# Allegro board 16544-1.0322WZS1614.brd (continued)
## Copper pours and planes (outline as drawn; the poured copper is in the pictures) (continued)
AMP_SPKR_L-_C on TOP: 216.41,5.26 216.41,8.99 216.13,9.27 216.13,11.07 216.2,11.15 218.31,11.15 218.59,10.87 218.59,10.34 218.39,10.14 217.86,10.14 217.84,10.12 217.69,10.12 217.09,9.53 217.09,5.28 217.07,5.26
AMP_SPKR_R+_C on TOP: 213.39,5.23 213.23,5.38 213.23,8.76 212.88,9.12 210.26,9.12 210.25,9.11 208.39,9.11 207.47,10.03 205.87,10.03 205.49,10.41 205.49,12.6 205.64,12.75 206.76,12.75 206.88,12.88 208.64,12.88 208.66,12.85 208.66,10.46 208.97,10.16 213.23,10.16 214.25,9.14 214.25,5.38 214.1,5.23 ; 1 cut-out
AMP_SPKR_R-_C on TOP: 214.91,5.26 214.91,8.74 214.9,8.75 214.9,9 214.88,9.02 214.88,9.19 213.61,10.46 213.18,10.46 213.06,10.59 213.06,11.2 213.27,11.42 215.56,11.42 215.77,11.2 215.77,8.94 215.6,8.76 215.6,5.26
AUO_PVDD1 on BOTTOM: 194.36,41.1 194.06,41.4 193.29,41.4 193.22,41.48 193.22,43.03 193.68,43.48 197.97,43.48 198.12,43.33 198.12,41.53 197.99,41.4 195.33,41.4 195.02,41.1 ; 4 cut-outs
DC_19V on TOP: 29.49,110.24 29.34,110.39 29.34,112.01 27.81,113.54 27.81,123.44 27.94,123.57 33.02,123.57 33.71,122.89 33.71,110.69 33.25,110.24 ; 2 cut-outs
DC_19V on BOTTOM: 29.03,112.45 27.81,113.67 27.81,123.06 28.07,123.32 32.64,123.32 33.53,122.43 33.53,112.65 33.32,112.45 ; 1 cut-out
EC_3D3V_AUX_S5 on TOP: 101.85,74.93 101.6,75.18 100.97,75.18 100.84,75.31 100.84,75.69 101.09,75.95 102.36,75.95 103.12,76.71 103.12,77.98 102.87,78.23 100.58,78.23 100.2,78.61 100.2,79.5 100.33,79.63 100.33,81.03 100.46,81.15 102.87,81.15 104.01,80.01 104.01,75.95 103,74.93 ; 3 cut-outs
IPCC_AGND on BOTTOM: 17.6,132.08 16.66,133.02 16.66,135.87 16.26,136.27 15.88,136.27 15.75,136.4 15.75,136.78 15.88,136.91 16.28,136.91 16.66,137.29 16.66,139.01 16.92,139.27 21.06,139.27 21.44,138.89 21.44,137.21 21.67,136.98 21.67,134.84 21.51,134.68 18.61,134.68 18.24,134.32 18.24,133.71 18.8,133.15 18.8,133.1 19.05,132.84 19.05,132.33 18.8,132.08 ; 6 cut-outs
Net_67 on BOTTOM: 119,84.45 119,83.31 123.44,83.31 123.44,84.45
Net_68 on BOTTOM: 125.04,56.39 129.62,56.39 129.62,58.39 125.04,58.39
PWR_0D8V on TOP: 115.04,192.56 114.68,192.91 114.68,193.22 113.46,194.44 113.46,197.89 113.67,198.09 119.28,198.09 119.58,197.79 119.58,192.91 119.23,192.56
PWR_0D8V on BOTTOM: 113.64,192.02 113.46,192.2 113.46,197.89 113.67,198.09 119.28,198.09 119.58,197.79 119.58,193.55 119.41,193.37 119.41,192.48 119.1,192.18 117.32,192.18 117.2,192.3 115.14,192.3 114.86,192.02
PWR_0D8V_FB_A on BOTTOM: 119.76,205.87 119.38,206.25 119.38,207.14 119.63,207.39 121.41,207.39 121.54,207.26 121.54,206.88 120.52,205.87 ; 1 cut-out
PWR_0D8V_PH on TOP: 114.76,199.31 113.84,200.23 113.84,203.07 114.22,203.45 118.82,203.45 119.1,203.17 119.1,200 118.41,199.31
PWR_0D8V_PH on BOTTOM: 114.54,199.63 113.69,200.48 113.69,202.37 113.35,202.72 112.62,202.72 112.52,202.82 112.52,203.38 113.82,204.67 113.92,204.67 114.07,204.83 114.12,204.83 114.55,205.26 114.71,205.26 114.81,205.16 114.81,203.66 115.42,203.05 118.08,203.05 118.41,202.72 118.41,200 118.05,199.63 ; 1 cut-out
PWR_0D8V_PH on L6: 114.58,208.23 114.58,203.63 115.23,202.98 116.17,202.98 118.75,200.41 118.75,199.64 118.36,199.26 114.68,199.26 113.51,200.43 113.51,208.79 113.56,208.84 113.97,208.84
PWR_0D8V_VCC on BOTTOM: 116.08,203.71 115.54,204.24 115.54,205.33 115.57,205.36 115.7,205.36 115.95,205.1 116.15,205.1 116.23,205.03 116.23,204.83 116.33,204.72 119.13,204.72 119.25,204.6 119.25,203.84 119.13,203.71
PWR_0D9V_VIN on TOP: 138.68,204.98 138.3,205.36 138.3,207.77 137.92,208.15 136.65,208.15 136.4,208.41 136.4,209.68 135.76,210.31 135.76,212.09 136.27,212.6 137.67,212.6 137.79,212.47 137.79,211.33 138.18,210.95 138.18,209.55 138.43,209.3 141.22,209.3 141.35,209.17 141.35,205.23 141.1,204.98 ; 2 cut-outs
PWR_0D775V on TOP: 123.01,207.65 122.86,207.8 122.86,209.91 122.71,210.06 122.71,211.02 122.43,211.3 122.43,213.23 122.68,213.49 123.57,213.49 124.08,212.98 124.08,212.34 123.83,212.09 123.83,209.73 123.52,209.42 123.52,207.87 123.29,207.65 ; 4 cut-outs
PWR_1D2V on TOP: 223.39,97.54 222.94,97.99 222.94,108.76 224.46,110.29 230.33,110.29 231.27,109.35 231.27,107.92 228.6,105.26 228.6,97.92 228.22,97.54
PWR_1D2V on TOP: 229.18,132.03 228.12,133.1 226.31,133.1 226.06,133.35 226.06,134.37 226.19,134.49 227.71,134.49 227.9,134.31 227.9,134.32 230.45,134.32 230.78,133.99 230.78,132.31 230.5,132.03
PWR_1D2V on BOTTOM: 223.39,97.54 222.76,98.17 222.76,108.58 224.49,110.31 230.35,110.31 231.29,109.37 231.29,108.23 230.76,107.7 228.85,107.7 228.6,107.44 228.6,97.92 228.22,97.54
PWR_1D2V on L3: 228.85,133.86 228.85,132.33 229.11,132.08 231.14,132.08 231.78,131.44 232.94,131.44 233.3,131.8 233.3,132.46 231.52,134.24 229.24,134.24
PWR_1D5V on TOP: 140.34,127.38 140.21,127.51 137.85,127.51 137.68,127.67 137.68,129.4 137.79,129.51 137.79,132.44 137.87,132.51 138.79,132.51 139.17,132.13 141.05,132.13 141.1,132.08 141.1,129.41 140.97,129.29 140.97,129.26 140.89,129.18 140.89,127.43 140.84,127.38 ; 6 cut-outs
PWR_1D05V on TOP: 143.61,26.34 143.51,26.44 143.51,33.02 143.13,33.4 143.13,33.78 143.26,33.91 147.12,33.91 147.24,33.78 147.24,32.33 147.7,31.88 147.7,26.67 147.37,26.34
PWR_1D05V on BOTTOM: 143.64,30.35 143.51,30.48 143.51,32.26 144.4,33.15 146.69,33.15 147.7,32.13 147.7,30.61 147.45,30.35
PWR_1D5V_PH on TOP: 146.18,18.29 145.16,19.3 143.76,19.3 143.51,19.56 143.51,22.53 143.87,22.89 147.12,22.89 147.24,22.76 147.24,20.47 147.12,20.35 146.94,20.35 146.48,19.89 146.48,19.51 146.69,19.3 146.69,18.39 146.58,18.29 ; 1 cut-out
PWR_1D5V_PH on BOTTOM: 145.11,14.76 145.03,14.83 145.03,16.38 145.02,16.4 145.02,17.84 144.4,18.47 144.4,19.94 144.58,20.12 146.05,20.12 146.28,19.89 146.28,15.06 145.97,14.76
PWR_1D5V_VIN on TOP: 134.67,125.4 134.49,125.58 134.49,128.47 134.19,128.78 132.59,128.78 132.08,129.29 132.08,131.57 132.49,131.98 134.24,131.98 134.32,131.9 134.32,130.18 134.49,130 136.83,130 137.31,129.51 137.31,125.45 137.26,125.4 ; 2 cut-outs
PWR_1D8V on TOP: 132.74,117.07 131.7,118.11 131.7,122.17 132.21,122.68 137.54,122.68 137.67,122.56 137.67,117.68 137.06,117.07
PWR_1D8V on BOTTOM: 131.95,119.41 131.72,119.63 131.72,122.05 132.23,122.56 136.78,122.56 137.34,122 137.34,119.81 136.93,119.41
PWR_1D8V_PH on TOP: 133.93,109.04 132.87,110.11 132.74,110.11 131.9,110.95 131.9,113.54 132.36,114 136.3,114 136.45,113.84 136.45,111.33 136.32,111.2 135.03,111.2 134.37,110.54 134.37,109.14 134.26,109.04
PWR_1D8V_PH on BOTTOM: 132.84,105.28 132.72,105.41 132.72,109.98 132.33,110.36 132.33,110.87 132.72,111.25 133.35,111.25 133.73,110.87 133.73,105.41 133.6,105.28
PWR_1D8V_VGA on TOP: 95.12,155.32 95.12,156.97 95.38,157.23 95.76,157.23 95.89,157.35 95.89,159.89 95.55,160.22 95.55,160.58 95.61,160.63 97.13,160.63 97.14,160.64 97.57,160.64 98.22,161.29 98.22,162.18 98.3,162.26 99.77,162.26 99.77,162.23 99.85,162.15 99.85,156.36 98.81,155.32 ; 6 cut-outs
PWR_1D8V_VGA_VIN on TOP: 101.47,156.97 100.2,158.24 100.2,162.94 100.46,163.19 102.74,163.19 103,162.94 103,159.89 103.12,159.77 105.03,159.77 106.3,158.5 107.82,158.5 107.95,158.62 108.2,158.62 108.33,158.5 108.33,157.1 108.2,156.97 ; 2 cut-outs
PWR_1D35V on TOP: 34.44,212.7 34.16,212.98 28.83,212.98 28.45,213.36 28.45,219.84 28.96,220.34 36.32,220.34 37.21,219.46 37.21,213.44 36.47,212.7
PWR_1D35V on BOTTOM: 28.7,212.98 28.32,213.36 28.32,220.34 28.96,220.98 36.7,220.98 37.21,220.47 37.21,213.61 36.58,212.98
PWR_1D35V_PH on TOP: 10.67,212.47 10.54,212.6 10.54,213.61 10.29,213.87 10.29,215.39 10.54,215.65 12.19,215.65 12.32,215.52 12.32,214 10.79,212.47 ; 1 cut-out
PWR_1D35V_PH on TOP: 19.38,210.29 19.1,210.57 19.1,215.93 19.28,216.1 22.94,216.1 23.29,216.46 23.29,218.06 22.66,218.69 22.66,222.35 22.81,222.5 26.54,222.5 27.05,222 27.05,210.82 26.52,210.29
PWR_1D35V_PH on BOTTOM: 19.41,210.29 19.18,210.52 19.18,215.65 19.68,216.15 22.48,216.15 22.86,216.53 22.86,222.25 23.11,222.5 26.54,222.5 27.05,222 27.05,210.82 26.52,210.29
PWR_2D5V on TOP: 136.7,71.45 136.55,71.6 136.55,75.97 138.05,77.47 138.81,77.47 138.93,77.36 138.93,75.45 139,75.37 138.99,75.36 138.99,73.71 138.68,73.41 138.68,71.58 138.56,71.45 ; 7 cut-outs
PWR_2D5V_PCH on TOP: 137.34,60.1 137.12,60.31 136.92,60.31 136.91,60.33 135,60.33 135,62.38 135.41,62.79 137.01,62.79 137.36,63.14 139.62,63.14 140.13,62.64 140.13,60.6 139.62,60.1 ; 7 cut-outs
PWR_2D5V_PCH_FB on TOP: 137.44,58.04 137.36,58.12 137.36,58.57 136.83,59.11 135.03,59.11 134.98,59.16 134.98,59.69 135.03,59.74 137.24,59.74 137.29,59.79 138.76,59.79 139.19,59.36 139.19,58.42 138.81,58.04 ; 4 cut-outs
PWR_2D5V_PCH_VIN on TOP: 131.78,58.34 131.75,58.37 131.75,61.54 131.67,61.62 129.77,61.62 129.67,61.72 129.67,63.75 130.3,64.39 134.11,64.39 134.37,64.14 134.37,62.1 134.62,61.85 134.62,58.45 134.52,58.34 ; 1 cut-out
PWR_2D5V_VIN on TOP: 134.42,66.29 134.29,66.42 134.29,67.21 134.62,67.54 134.62,70.61 135.1,71.09 140.44,71.09 140.67,70.87 140.67,68.58 140.41,68.33 137.67,68.33 137.41,68.07 137.41,66.42 137.29,66.29 ; 1 cut-out
PWR_3D3V on TOP: 125.48,17.07 124.97,17.58 124.97,22.91 125.3,23.24 137.03,23.24 137.46,23.67 137.67,23.67 137.92,23.42 137.92,18.29 137.79,18.41 131.83,18.41 130.48,17.07
PWR_3D3V on BOTTOM: 125.48,17.07 124.97,17.58 124.97,22.91 125.32,23.27 136.93,23.27 137.34,23.67 137.67,23.67 137.92,23.42 137.92,18.03 137.41,18.03 136.91,18.54 132.54,18.54 131.06,17.07
PWR_3D3V_PH2 on TOP: 122.2,13.44 121.79,13.84 117.98,13.84 116.84,14.99 116.84,25.15 117.35,25.65 122.56,25.65 123.32,24.89 123.32,13.72 123.04,13.44
PWR_3D3V_PH2 on BOTTOM: 118.87,12.95 118.62,13.21 118.62,19.18 117.98,19.81 114.94,19.81 114.81,19.94 114.81,25.35 114.99,25.53 122.81,25.53 123.44,24.89 123.44,14.15 122.86,13.56 122.02,13.56 121.79,13.79 120.45,13.79 120.24,13.59 120.24,13.18 120.02,12.95
PWR_5V on TOP: 125.02,32.21 124.46,32.77 124.46,38.35 124.97,38.86 134.11,38.86 135.46,37.52 136.91,37.52 137.34,37.08 138.05,37.08 138.05,32.69 137.57,32.21
PWR_5V on BOTTOM: 125.02,32.21 124.46,32.77 124.46,38.35 124.97,38.86 137.67,38.86 138.05,38.48 138.05,32.26 138,32.21
PWR_5V_HG1 on TOP: 103.43,32.05 103.35,32.13 103.35,32.72 104.47,33.83 104.47,34.11 104.62,34.26 105.26,34.26 105.41,34.11 105.41,33.92 104.19,32.7 104.18,32.7 103.53,32.05
PWR_5V_LG1 on TOP: 103.73,31.45 103.71,31.47 103.71,31.65 103.81,31.75 104.11,31.75 104.24,31.88 104.62,31.88 105.21,32.46 105.54,32.46 105.79,32.21 105.79,32 105.41,31.62 104.9,31.62 104.72,31.45
PWR_5V_PH1 on TOP: 117.47,28.07 116.59,28.96 116.59,38.61 117.86,39.88 122.05,39.88 122.94,38.99 122.94,28.96 122.05,28.07
PWR_5V_PH1 on BOTTOM: 114.94,26.67 114.81,26.8 114.81,32.13 114.94,32.26 118.36,32.26 118.87,32.77 118.87,34.57 119.25,34.95 121.03,34.95 121.36,35.28 121.36,36.88 121.11,37.13 118.69,37.13 118.62,37.21 118.62,40.26 118.87,40.51 121.44,40.51 122.94,39.01 122.94,28.96 120.65,26.67
PWR_12V on TOP: 8.64,183.51 8,184.15 8,187.32 8.38,187.71 13.84,187.71 13.97,187.58 13.97,184.28 13.21,183.51 ; 4 cut-outs
PWR_12V on BOTTOM: 8.38,183.64 8,184.02 8,188.34 8.38,188.72 12.95,188.72 14.1,187.58 14.1,184.02 13.72,183.64
PWR_12V_BOOT on BOTTOM: 12.01,195.58 11.76,195.83 11.76,196.52 11.91,196.67 12.9,196.67 13.61,197.38 13.61,197.97 13.87,198.22 14.38,198.22 14.63,197.97 14.63,195.66 14.55,195.58
PWR_12V_FB on BOTTOM: 7.32,198.7 7.19,198.83 7.19,200.43 6.81,200.81 6.81,201.4 7.04,201.63 7.98,201.63 9.04,200.56 9.04,200.38 9.53,199.9 9.53,199.24 9.35,199.06 8.13,199.06 7.77,198.7 ; 4 cut-outs
PWR_12V_LX on TOP: 13.08,192.02 12.45,192.66 12.45,195.33 12.7,195.58 16,195.58 16.26,195.33 16.26,192.91 15.37,192.02 ; 1 cut-out
PWR_12V_LX on BOTTOM: 8.89,192.02 8.51,192.41 8.51,194.69 9.27,195.45 10.29,195.45 10.38,195.54 10.38,196.61 10.49,196.72 11.3,196.72 11.46,196.57 11.46,195.55 12.7,194.31 14.1,194.31 14.35,194.06 14.35,192.28 14.1,192.02
PWR_19V_DCBATOUT_RT6575 on BOTTOM: 106.43,29.08 106.17,29.34 106.17,31.11 105.92,31.37 105.92,32.64 106.05,32.77 107.19,32.77 108.56,31.39 108.56,29.46 108.18,29.08
PWR_DCBATOUT_0D8V on BOTTOM: 110.74,204.34 110.62,204.47 110.62,209.75 111.26,210.4 111.26,211.81 112.89,213.44 112.89,215.33 113.56,216 115.11,216 115.72,215.39 115.72,213.49 115.7,213.49 115.7,213.23 114.76,212.29 114.76,210.92 113.94,210.11 113.94,209.75 113.21,209.02 113.21,208.43 113.84,207.8 113.84,207.31 114.35,206.81 114.35,205.79 114.22,205.66 113.28,205.66 113.23,205.71 112.37,205.71 112.01,205.36 112.01,204.6 111.76,204.34
PWR_DCBATOUT_1D05V on TOP: 146.56,8.99 146.44,9.11 145.58,9.11 144.81,9.88 143.41,9.88 142.75,10.54 142.75,16.13 143.05,16.43 143.05,17.35 143.23,17.53 144.78,17.53 144.91,17.65 145.92,17.65 146.05,17.53 146.05,16.38 145.72,16.05 145.06,16.05 144.73,15.72 144.73,14.76 145.11,14.38 145.11,13.16 145.26,13 145.26,11.76 145.8,11.23 146.94,11.23 147.02,11.15 147.02,9.09 146.91,8.99 ; 1 cut-out
PWR_DCBATOUT_1D8V on TOP: 129.67,105.28 129.41,105.54 129.41,108.08 129.79,108.46 129.79,108.76 129.9,108.86 131.19,108.86 131.22,108.84 133.6,108.84 133.86,108.58 133.86,107.72 133.3,107.16 133.3,106.88 131.7,105.28 ; 2 cut-outs
PWR_DCBATOUT_1D8V on BOTTOM: 129.41,105.03 129.29,105.16 129.29,107.67 130,108.38 131.98,108.38 132.09,108.27 132.09,105.17 131.95,105.03
PWR_DCBATOUT_1D35V on TOP: 12.8,218.82 12.67,218.95 12.67,222.15 12.99,222.47 13.96,222.47 15.11,223.62 16.43,223.62 17.12,224.31 21.95,224.31 22.15,224.1 22.15,219.05 21.92,218.82
PWR_DCBATOUT_1D35V on BOTTOM: 12.42,218.82 11.81,219.43 11.81,221.77 12.32,222.28 13.74,222.28 14.86,223.39 16,223.39 16.89,222.5 16.89,219.46 16.26,218.82 ; 2 cut-outs
PWR_DCBATOUT_3D3V on TOP: 108.98,12.46 108.39,13.04 108.39,14.49 109.22,15.32 109.73,15.32 111.18,16.76 115.04,16.76 115.09,16.71 115.09,13.89 113.67,12.47 108.99,12.47
PWR_DCBATOUT_3D3V on BOTTOM: 107.82,11.18 107.57,11.43 107.57,14.48 107.7,14.61 109.09,14.61 111.12,16.64 112.9,16.64 113.03,16.76 118.24,16.76 118.36,16.64 118.36,11.3 118.24,11.18 ; 2 cut-outs
PWR_DCBATOUT_5V on TOP: 108.2,35.43 107.95,35.69 107.95,38.35 109.47,39.88 112.27,39.88 113.28,38.86 113.28,36.32 112.39,35.43
PWR_DCBATOUT_5V on BOTTOM: 108.05,35.43 107.25,36.23 107.25,40.53 107.62,40.89 118.24,40.89 118.36,40.77 118.36,35.56 118.24,35.43 ; 2 cut-outs
PWR_DCBATOUT_12V on TOP: 12.19,200.91 12.06,201.04 12.06,203.58 12.32,203.84 14.48,203.84 14.61,203.71 14.61,201.04 14.48,200.91
PWR_DCBATOUT_12V on BOTTOM: 11.43,199.01 11.3,199.14 11.3,200.15 11.94,200.79 11.94,201.93 12.45,202.44 12.45,205.23 12.57,205.36 14.22,205.36 14.61,204.98 14.61,200.15 13.46,199.01 ; 2 cut-outs
PWR_DCBATOUT_VCOREA on TOP: 188.21,213.77 187.68,214.3 187.68,227.3 188.21,227.84 193.09,227.84 193.98,226.95 193.98,219.46 193.52,219 193.52,213.92 193.37,213.77 ; 2 cut-outs
PWR_DCBATOUT_VCOREA on BOTTOM: 188.24,213.77 187.68,214.33 187.68,227.33 188.35,228 193.17,228 194.06,227.11 194.06,223.27 194.69,222.63 194.69,222.15 194.13,221.59 194.13,219.61 193.52,219 193.52,213.92 193.37,213.77 ; 2 cut-outs
PWR_DCBATOUT_VCOREB on TOP: 171.96,213.64 171.75,213.84 171.75,228.85 172.11,229.21 172.92,229.21 173.05,229.08 176.1,229.08 177.39,227.79 177.39,213.82 177.22,213.64 ; 2 cut-outs
PWR_DCBATOUT_VCOREB on BOTTOM: 171.96,213.64 171.75,213.84 171.75,228.93 172.19,229.36 175.82,229.36 178.21,226.97 178.21,222.15 177.88,221.82 177.88,220.19 177.39,219.71 177.39,213.82 177.22,213.64 ; 2 cut-outs
PWR_DCBATOUT_VCOREC on TOP: 155.78,213.44 155.42,213.79 155.42,218.44 155.73,218.74 157.02,218.74 157.15,218.87 157.15,225.37 156.72,225.81 156.72,228.6 157.18,229.06 161.77,229.06 162.15,228.68 162.15,220.98 161.26,220.09 161.26,219.1 160.93,218.77 160.93,213.59 160.78,213.44 ; 2 cut-outs
PWR_DCBATOUT_VCOREC on BOTTOM: 155.59,213.63 155.42,213.79 155.42,218.47 155.68,218.72 156.97,218.72 157.15,218.9 157.15,225.37 156.72,225.81 156.72,228.96 157.02,229.26 161.72,229.26 162.15,228.83 162.15,219.96 160.96,218.77 160.96,214.25 160.34,213.63 ; 2 cut-outs
PWR_DCBATOUT_VDDCA on TOP: 96.14,105.92 95.76,106.3 95.76,107.95 97.66,109.86 97.66,111.25 96.82,112.09 96.82,115.34 96.88,115.39 96.88,117.17 96.98,117.27 98.12,117.27 98.25,117.4 98.25,118.24 98.3,118.29 99.59,118.29 99.69,118.19 99.69,114.71 101.47,112.93 101.47,109.09 98.3,105.92
PWR_DCBATOUT_VDDCA on BOTTOM: 99.16,111.89 98.91,112.14 98.91,118.26 99.01,118.36 99.77,118.36 99.9,118.24 99.9,116.28 100.18,116 100.97,116 101.35,115.62 101.35,112.27 100.97,111.89
PWR_DCBATOUT_VDDCB on TOP: 84.71,109.47 84.58,109.6 84.58,112.9 85.34,113.67 85.34,117.22 85.5,117.37 86.44,117.37 86.59,117.53 86.59,118.34 86.61,118.36 88.19,118.36 88.32,118.24 88.32,114.91 88.16,114.76 88.16,114.27 88.39,114.05 89.92,114.05 90.08,113.88 90.08,109.77 89.79,109.47 ; 1 cut-out
PWR_DCBATOUT_VDDCB on BOTTOM: 86.74,112.65 86.49,112.9 86.49,115.29 87.38,116.18 87.38,118.26 87.48,118.36 88.24,118.36 88.37,118.24 88.37,116.28 88.65,116 89.43,116 89.89,115.54 89.89,113.26 89.28,112.65 ; 2 cut-outs
PWR_DCBATOUT_VDDCC on TOP: 72.69,109.52 72.54,109.68 69.85,109.68 69.58,109.94 69.58,113.5 71.45,115.37 73.74,115.37 74.24,115.87 74.24,117.32 74.3,117.37 75.34,117.37 75.49,117.53 75.49,118.34 75.51,118.36 77.09,118.36 77.22,118.24 77.22,115.34 77.01,115.14 77.01,113.72 76.35,113.06 76.35,109.68 76.2,109.52 ; 2 cut-outs
PWR_DCBATOUT_VDDCC on BOTTOM: 76.2,112.52 75.31,113.41 75.31,115.32 76.28,116.28 76.28,118.26 76.38,118.36 77.14,118.36 77.27,118.24 77.27,116.28 77.95,115.6 77.95,112.75 77.72,112.52
PWR_DCBATOUT_VDDCD on TOP: 57.73,109.5 57.58,109.65 57.58,110.36 57.91,110.69 57.94,110.69 58.6,111.35 58.6,112.47 59.44,113.31 59.44,114.1 59.82,114.48 59.82,115.35 59.83,115.35 59.83,115.51 59.84,115.52 59.84,117.35 59.89,117.4 60.93,117.4 61.09,117.55 61.09,118.36 61.11,118.39 62.69,118.39 62.81,118.26 62.81,114.25 63.58,113.49 64.14,113.49 64.57,113.06 64.57,109.78 64.31,109.52 62.61,109.52 62.59,109.55 60.99,109.55 60.93,109.5 ; 2 cut-outs
PWR_DCBATOUT_VDDCD on BOTTOM: 61.98,112.65 61.34,113.28 61.34,115.57 61.87,116.1 61.87,118.29 61.98,118.39 62.74,118.39 62.87,118.26 62.87,116.31 63.14,116.03 63.5,116.03 63.88,115.65 63.88,112.78 63.75,112.65
PWR_DCBATOUT_VDDCE on TOP: 48.97,110.03 48.9,110.11 48.9,115.57 48.72,115.75 48.72,117.35 48.77,117.4 49.81,117.4 49.96,117.55 49.96,118.36 49.99,118.39 51.56,118.39 51.69,118.26 51.69,115.01 51.54,114.86 51.54,114.45 51.94,114.05 53.45,114.05 53.46,114.04 54.24,114.04 54.36,113.92 54.36,110.74 54.23,110.62 50.24,110.62 50.06,110.44 50.06,110.13 49.96,110.03 ; 3 cut-outs
PWR_DCBATOUT_VDDCE on BOTTOM: 50.55,112.52 50.39,112.67 50.39,116.15 50.75,116.51 50.75,118.29 50.85,118.39 51.61,118.39 51.74,118.26 51.74,116.54 52.25,116.03 53.11,116.03 53.39,115.75 53.39,112.7 53.21,112.52
PWR_DCBATOUT_VDDCF on TOP: 37.47,110.24 37.34,110.36 37.34,115.14 37.62,115.42 37.62,117.2 37.82,117.4 38.71,117.4 38.86,117.55 38.86,118.36 38.89,118.39 40.46,118.39 40.59,118.26 40.59,114.68 41.02,114.25 42.01,114.25 42.67,113.59 42.67,113.03 42.8,112.9 42.8,110.62 42.55,110.36 38.73,110.36 38.61,110.24 ; 2 cut-outs
PWR_DCBATOUT_VDDCF on BOTTOM: 38.99,112.52 38.86,112.65 38.86,115.8 39.65,116.59 39.65,118.29 39.75,118.39 40.51,118.39 40.64,118.26 40.64,116.66 41.91,115.39 41.91,112.65 41.78,112.52
PWR_DCBATOUT_VDDCI on TOP: 140.08,218.95 139.95,219.07 139.95,220.09 139.83,220.22 139.45,220.22 139.06,220.6 139.06,221.62 139.45,222 142.49,222 142.56,222.06 144.78,222.06 145.73,223.01 146.81,223.01 147.83,224.03 148.72,224.03 148.97,223.77 148.97,219.81 148.11,218.95
PWR_DCBATOUT_VDDCI on BOTTOM: 143.13,218.82 142.75,219.2 142.75,221.79 143.03,222.07 144.86,222.07 145.54,222.76 145.54,226.57 146.05,227.08 148.46,227.08 148.84,226.69 148.84,219.96 147.7,218.82 ; 2 cut-outs
PWR_DCBATOUT_VDDNBA on TOP: 212.09,190.88 211.81,191.16 211.85,191.2 211.85,196.39 211.95,196.49 215.11,196.49 216.08,197.46 216.08,198.07 216.59,198.58 219.23,198.58 219.33,198.48 219.53,198.48 219.53,191.21 219.2,190.88 ; 3 cut-outs
PWR_DCBATOUT_VDDNBA on BOTTOM: 212.01,190.91 211.79,191.13 211.79,196.37 211.91,196.49 215.49,196.49 215.49,196.52 216,197.03 216,198.65 216.41,199.06 219.02,199.06 219.56,198.53 219.56,191.11 219.51,191.06 217.22,191.06 217.07,190.91
PWR_DCBATOUT_VDDNBB on TOP: 223.19,191.16 223.06,191.29 223.06,198.53 225.86,201.32 228.32,201.32 228.59,201.05 228.59,200.27 228.6,200.25 228.6,199.26 228.85,199.01 228.85,197.49 228.3,196.93 228.3,191.41 228.04,191.16 ; 2 cut-outs
PWR_DCBATOUT_VDDNBB on BOTTOM: 223.22,191.19 223.06,191.34 223.06,197.43 224.35,198.72 224.35,200.6 224.66,200.91 228.22,200.91 228.35,200.79 228.35,199.31 228.93,198.73 228.93,197.61 228.27,196.95 228.27,191.49 227.97,191.19
PWR_DCBATOUT_VDDP on TOP: 149.99,213.61 149.99,225.63 150.34,225.98 152.98,225.98 153.03,225.93 153.03,219.96 151.38,218.31 151.38,214.12 150.88,213.61
PWR_DCBATOUT_VDDP on BOTTOM: 150.11,213.49 149.86,213.74 149.86,218.31 149.73,218.44 149.73,225.55 150.37,226.19 152.78,226.19 153.16,225.81 153.16,220.34 152.48,219.66 152.48,218.64 151.51,217.68 151.38,217.68 151.13,217.42 151.13,213.49 ; 4 cut-outs
PWR_DCBATOUT_VDDQ on TOP: 225.81,122.05 225.55,122.3 225.55,127.38 225.93,127.76 225.93,132.08 225.68,132.33 225.68,132.72 225.81,132.84 227.2,132.84 228.35,131.7 230.76,131.7 231.39,131.06 231.39,122.3 231.14,122.05 ; 1 cut-out
PWR_DCBATOUT_VDDQ on BOTTOM: 225.68,122.05 225.55,122.17 225.55,127.33 225.93,127.71 225.93,131.62 225.98,131.67 227.23,131.67 227.46,131.44 229.24,131.44 229.49,131.7 230.89,131.7 231.39,131.19 231.39,122.3 231.14,122.05
PWR_VCORE_VDD on TOP: 207.52,215.39 207.14,215.77 207.14,216.41 207.9,217.17 207.9,218.44 208.53,219.07 209.04,219.07 209.3,218.82 209.3,215.52 209.17,215.39 ; 2 cut-outs
PWR_VCORE_VIN on TOP: 208.66,221.11 208.53,221.23 208.53,223.65 208.66,223.77 210.95,223.77 211.07,223.65 211.07,221.23 210.95,221.11 ; 1 cut-out
PWR_VCOREA_HG on BOTTOM: 206.63,214.63 206.35,214.91 206.35,215.62 207.2,216.47 209,216.47 209.02,216.48 210.82,216.48 210.95,216.61 211.33,216.61 211.53,216.41 211.53,215.85 210.69,215.01 208.79,215.01 208.76,214.99 207.85,214.99 207.49,214.63
PWR_VCOREA_HG_A on TOP: 192.43,211.02 192.28,211.18 192.28,213.39 192.33,213.44 193.01,213.44 193.04,213.41 193.04,211.2 192.86,211.02
PWR_VCOREA_HG_A on BOTTOM: 186.89,209.68 186.79,209.78 186.79,210.97 187.53,211.71 188.09,211.71 188.47,212.09 188.47,213.39 188.52,213.44 189.2,213.44 189.23,213.41 189.23,211.12 189.42,210.93 189.42,209.97 189.13,209.68 ; 1 cut-out
PWR_VCOREA_LG on TOP: 197.69,217.6 197.61,217.68 197.61,220.09 197.74,220.22 198.25,220.22 198.37,220.09 198.37,217.68 198.3,217.6
PWR_VCOREA_LG on BOTTOM: 201.47,217.6 201.42,217.65 201.42,219.84 201.93,220.34 202.82,220.34 203.07,220.09 203.07,218.54 202.13,217.6
PWR_VCOREA_PH on TOP: 188.93,203.66 188.48,204.1 188.48,209.41 188.01,209.88 188.01,213.28 188.19,213.46 191.64,213.46 191.77,213.33 191.77,210.97 192.1,210.64 193.34,210.64 193.73,211.02 193.73,212.8 194.46,213.54 196.55,213.54 197.1,214.1 197.1,217.07 197.31,217.27 202.49,217.27 202.67,217.09 202.67,208.99 202.08,208.41 198.88,208.41 197.18,206.71 195.76,206.71 195.75,206.72 194.93,206.72 194.59,206.38 194.56,206.38 193.68,205.49 192.79,205.49 192.53,205.23 192.53,203.86 192.33,203.66
PWR_VCOREA_PH on BOTTOM: 204.8,216.2 204.57,216.43 204.57,217.14 205.74,218.31 205.74,218.34 208.84,218.34 209.42,217.75 209.42,217.22 209.25,217.04 206.25,217.04 205.41,216.2
PWR_VCOREA_PH on BOTTOM: 189.1,203.71 188.75,204.06 188.75,208.69 189.71,209.65 189.71,213.31 189.84,213.44 196.44,213.44 197.1,214.1 197.1,217.07 197.31,217.27 202.49,217.27 202.67,217.09 202.67,208.99 202.08,208.41 198.81,208.41 196.89,206.49 194.81,206.49 194.56,206.25 194.56,204.17 194.11,203.71 ; 2 cut-outs
PWR_VCOREB_BOOT on BOTTOM: 209.85,222 208.46,223.39 207.26,223.39 207.26,224.74 207.34,224.82 208.51,224.82 210.21,223.11 210.21,222.12 210.08,222
PWR_VCOREB_HG on BOTTOM: 204.6,221.36 204.34,221.62 204.34,222.25 204.98,222.88 208.28,222.88 208.97,222.2 208.97,221.84 208.79,221.67 205.87,221.67 205.56,221.36
PWR_VCOREB_HG_A on TOP: 176.12,210.9 176.02,211 176.02,213.26 176.1,213.33 176.71,213.33 176.78,213.26 176.78,210.97 176.71,210.9
PWR_VCOREB_HG_A on BOTTOM: 170.08,209.8 169.93,209.96 169.93,211.07 170.31,211.46 170.31,211.96 170.69,212.34 171.83,212.34 172.21,212.72 172.21,213.28 172.26,213.33 172.92,213.33 172.97,213.28 172.97,211.07 172.47,210.57 172.47,210.06 172.21,209.8 ; 1 cut-out
PWR_VCOREB_LG on TOP: 181.23,217.5 181.15,217.58 181.15,219.76 181.31,219.91 181.79,219.91 181.91,219.79 181.91,217.55 181.86,217.5
PWR_VCOREB_LG on BOTTOM: 185.01,217.5 184.96,217.55 184.96,219.71 185.34,220.09 187.32,220.09 187.45,219.96 187.45,219.28 185.67,217.5
PWR_VCOREB_PH on TOP: 172.21,203.58 171.96,203.84 171.96,208.79 171.55,209.19 171.55,213.11 171.75,213.31 175.44,213.31 175.51,213.23 175.51,211.07 175.95,210.64 177.04,210.64 177.44,211.05 177.44,212.8 178.05,213.41 179.98,213.41 180.67,214.1 180.67,217.02 180.85,217.2 186.08,217.2 186.21,217.07 186.21,209.58 185.45,208.81 181.41,208.81 179.98,207.39 175.9,207.39 175.64,207.14 175.64,204.09 175.13,203.58
PWR_VCOREB_PH on BOTTOM: 172.97,207.26 172.19,208.05 172.19,209.19 172.8,209.8 172.8,210.52 172.85,210.57 173.13,210.57 173.46,210.9 173.46,213.21 173.56,213.31 177.95,213.31 178.05,213.41 179.98,213.41 180.67,214.1 180.67,217.02 180.85,217.2 186.08,217.2 186.21,217.07 186.21,209.58 185.42,208.79 181.61,208.79 180.09,207.26 ; 1 cut-out
PWR_VCOREB_PH on BOTTOM: 206.5,218.72 206.38,218.85 206.38,220.9 206.83,221.36 209.3,221.36 209.42,221.23 209.42,220.98 209.3,220.85 208.79,220.85 208.41,220.47 208.41,218.87 208.25,218.72
PWR_VCOREC_BOOT on BOTTOM: 211.38,222.38 211.33,222.43 211.33,222.68 210.87,223.14 210.69,223.14 208.69,225.15 208.51,225.15 207.77,225.88 207.77,226.82 209.04,226.82 209.3,226.57 209.3,225.68 211.07,223.9 211.18,223.9 211.84,223.24 211.84,222.5 211.71,222.38
PWR_VCOREC_HG on BOTTOM: 155.07,206.88 154.94,207.01 154.94,208.41 155.07,208.53 157.23,208.53 157.48,208.28 157.48,207.39 156.97,206.88
PWR_VCOREC_HG on BOTTOM: 211.84,223.65 209.8,225.68 209.8,228.83 210.01,229.03 210.74,229.03 211.07,228.7 211.07,225.81 212.09,224.79 212.09,223.77 211.96,223.65
PWR_VCOREC_HG_A on BOTTOM: 155.19,208.91 154.94,209.17 154.94,210.31 155.7,211.07 155.7,213.11 155.83,213.23 156.59,213.23 156.72,213.11 156.72,210.95 157.23,210.44 157.35,210.44 157.48,210.31 157.48,209.17 157.23,208.91 ; 1 cut-out
PWR_VCOREC_LG on BOTTOM: 168.78,217.55 168.53,217.81 168.53,219.84 168.66,219.96 170.56,219.96 171.2,219.33 171.2,218.82 169.93,217.55
PWR_VCOREC_PH on TOP: 156.21,203.45 155.99,203.67 155.99,209.16 155.45,209.7 155.45,212.85 155.73,213.13 159.13,213.13 159.21,213.06 159.21,210.77 159.54,210.44 160.73,210.44 160.95,210.65 160.95,211.11 161.67,211.84 161.67,213.16 161.77,213.26 163.75,213.26 164.26,213.77 164.26,217.12 164.41,217.27 169.62,217.27 169.85,217.04 169.85,209.22 169.06,208.43 163.73,208.43 163.73,208.41 162.2,206.88 159.79,206.88 159.52,206.62 159.52,206.6 159.46,206.54 159.46,203.78 159.13,203.45
PWR_VCOREC_PH on BOTTOM: 159.03,206.86 157.81,208.08 157.81,210.52 157.18,211.15 157.18,213.06 157.35,213.23 163.73,213.23 164.26,213.77 164.26,217.12 164.41,217.27 169.62,217.27 169.85,217.04 169.85,211.89 169.52,211.56 169.52,208.91 169.06,208.46 163.96,208.46 163.93,208.43 163.73,208.43 162.15,206.86 ; 2 cut-outs
PWR_VCOREC_PH on BOTTOM: 212.29,224.97 211.58,225.68 211.58,227.2 211.71,227.33 212.95,227.33 213.23,227.05 213.23,225.45 212.75,224.97
PWR_VDDCA_PH on TOP: 100.46,116.15 100.18,116.43 100.18,120.55 100.3,120.68 100.43,120.68 100.56,120.8 100.56,122.17 100.42,122.31 100.04,122.31 99.16,123.19 98.04,123.19 95.63,125.6 95.63,127.89 96.01,128.27 102.64,128.27 103.02,127.89 103.02,123.04 103.89,122.17 103.89,120.29 103.76,120.17 102.29,120.17 102.21,120.09 102.21,116.28 102.08,116.15
PWR_VDDCA_PH on BOTTOM: 97.03,124.46 95.5,125.98 95.5,129.54 96.27,130.3 102.23,130.3 103,129.54 103,125.86 102.49,125.35 99.95,125.35 99.06,124.46
PWR_VDDCA_PH on L6: 102.44,116.69 101.93,116.18 100.03,116.18 99.52,116.69 99.52,123.16 99.14,123.55 97.61,123.55 95.71,125.45 95.71,127.97 96.14,128.4 102.11,128.4 102.44,128.07
PWR_VDDCB_PH on TOP: 88.65,116.15 88.62,116.18 88.62,120.57 88.75,120.7 88.87,120.7 89,120.83 89,122.1 87.6,123.49 86.59,123.49 84.58,125.5 84.58,127.76 85.34,128.52 90.81,128.52 91.19,128.14 91.19,122.99 92.46,121.72 92.46,120.29 92.33,120.17 91.14,120.17 91.06,120.09 91.06,116.28 90.93,116.15
PWR_VDDCB_PH on BOTTOM: 85.85,124.21 84.33,125.73 84.33,129.29 85.09,130.05 91.06,130.05 91.82,129.29 91.82,125.6 90.42,124.21
PWR_VDDCB_PH on L6: 91.29,116.69 90.78,116.18 88.87,116.18 88.37,116.69 88.37,123.16 87.99,123.55 86.46,123.55 84.56,125.45 84.56,127.76 84.58,127.76 85.34,128.52 90.81,128.52 91.29,128.04
PWR_VDDCC_PH on TOP: 77.55,116.15 77.52,116.18 77.52,120.57 77.65,120.7 77.77,120.7 77.9,120.83 77.9,122.33 76.76,123.47 76.76,123.49 75.49,123.49 73.41,125.58 73.41,127.76 74.17,128.52 79.76,128.52 80.09,128.19 80.09,122.99 81.36,121.72 81.36,120.29 81.23,120.17 80.04,120.17 79.96,120.09 79.96,116.28 79.83,116.15
PWR_VDDCC_PH on BOTTOM: 74.8,124.21 73.28,125.73 73.28,129.29 74.04,130.05 80.01,130.05 80.77,129.29 80.77,125.6 79.38,124.21
PWR_VDDCC_PH on L6: 80.19,116.69 79.68,116.18 77.77,116.18 77.27,116.69 77.27,123.16 76.89,123.55 75.36,123.55 73.46,125.45 73.46,127.81 74.17,128.52 79.81,128.52 80.19,128.14
PWR_VDDCD_PH on TOP: 63.14,116.18 63.12,116.2 63.12,120.6 63.25,120.73 63.37,120.73 63.5,120.85 63.5,122.43 63.45,122.43 62.36,123.52 61.09,123.52 58.93,125.68 58.93,127.76 59.69,128.52 66.65,128.52 66.78,128.4 66.78,125.35 66.27,124.84 66.27,122.43 66.95,121.74 66.95,120.32 66.83,120.19 65.63,120.19 65.56,120.12 65.56,116.31 65.43,116.18
PWR_VDDCD_PH on BOTTOM: 59.82,124.71 58.55,125.98 58.55,129.41 59.44,130.3 66.04,130.3 66.8,129.54 66.8,125.86 65.66,124.71
PWR_VDDCD_PH on L6: 66.8,128.4 66.8,126.11 65.79,125.09 65.79,116.71 65.28,116.2 63.37,116.2 62.87,116.71 62.87,123.19 62.48,123.57 60.96,123.57 58.93,125.6 58.93,127.64 59.94,128.65 66.55,128.65
PWR_VDDCE_PH on TOP: 52.02,116.18 51.99,116.2 51.99,120.6 52.12,120.73 52.25,120.73 52.37,120.85 52.37,122.25 51.1,123.52 49.96,123.52 47.88,125.6 47.88,127.89 48.51,128.52 54.36,128.52 54.56,128.32 54.56,123.01 55.83,121.74 55.83,120.32 55.7,120.19 54.51,120.19 54.43,120.12 54.43,116.31 54.31,116.18
PWR_VDDCE_PH on BOTTOM: 49.28,124.33 47.75,125.86 47.75,129.41 48.51,130.18 54.48,130.18 55.24,129.41 55.24,125.73 53.85,124.33
PWR_VDDCE_PH on L6: 54.66,116.71 54.15,116.2 52.25,116.2 51.74,116.71 51.74,123.19 51.36,123.57 49.83,123.57 47.93,125.48 47.93,127.94 48.51,128.52 54.41,128.52 54.66,128.27
PWR_VDDCF_PH on TOP: 40.92,116.18 40.89,116.2 40.89,120.6 41.02,120.73 41.15,120.73 41.27,120.85 41.27,122.38 40.13,123.52 38.86,123.52 36.45,125.93 36.45,128.02 36.96,128.52 43.18,128.52 43.46,128.24 43.46,123.01 44.73,121.74 44.73,120.32 44.6,120.19 43.41,120.19 43.33,120.12 43.33,116.31 43.21,116.18
PWR_VDDCF_PH on BOTTOM: 38.23,123.83 36.7,125.35 36.7,128.91 37.47,129.67 43.43,129.67 44.2,128.91 44.2,125.22 42.8,123.83
PWR_VDDCF_PH on L6: 43.56,116.71 43.05,116.2 41.15,116.2 40.64,116.71 40.64,123.19 40.26,123.57 38.73,123.57 36.45,125.86 36.45,128.02 36.96,128.52 43.18,128.52 43.56,128.14
PWR_VDDCI_PH on TOP: 129.79,218.95 129.41,219.33 129.41,227.58 129.67,227.84 132.46,227.84 132.59,227.71 132.59,226.31 133.1,225.81 135.13,225.81 135.51,226.19 137.19,226.19 137.26,226.11 137.26,224.84 137.31,224.79 141.35,224.79 141.35,222.76 141.6,222.5 142.49,222.5 142.62,222.38 142.62,222.25 142.49,222.12 141.6,222.12 141.35,222.38 136.78,222.38 136.78,222.76 136.73,222.81 134.42,222.81 133.91,222.3 133.91,221.54 132.97,220.6 132.97,219.84 132.08,218.95
PWR_VDDCI_PH on BOTTOM: 130.18,219.07 129.41,219.84 129.41,227.33 129.92,227.84 134.24,227.84 137.41,224.66 140.84,224.66 141.22,224.28 141.22,222.38 140.97,222.12 135.25,222.12 134.87,222.5 134.37,222.5 132.72,220.85 132.72,219.46 132.33,219.07
PWR_VDDCI_PH on L3: 137.79,224.92 141.1,224.92 141.35,224.66 141.35,222.5 141.1,222.25 136.27,222.25 135.89,222.63 134.24,222.63 133.86,222.25 133.86,221.74 132.84,220.73 132.84,219.71 132.08,218.95 129.79,218.95 129.41,219.33 129.41,227.58 129.67,227.84 132.46,227.84 132.59,227.71 132.59,226.31 133.1,225.81 135.25,225.81 135.64,226.19 136.53,226.19
PWR_VDDNBA_HG_A on TOP: 208.15,194.94 208,195.1 208,195.66 208.36,196.01 209.37,196.01 209.47,195.91 209.47,195.1 209.32,194.94 ; 1 cut-out
PWR_VDDNBA_HG_A on BOTTOM: 208.18,195.2 208.03,195.35 208.03,195.76 208.13,195.86 208.76,195.86 210.44,197.54 210.44,197.92 210.9,198.37 212.22,198.37 212.34,198.25 212.34,197.23 212.09,196.98 211.56,196.98 211.33,196.75 211.33,195.33 211.2,195.2
PWR_VDDNBA_LG on BOTTOM: 216.03,181.23 215.65,181.61 215.65,183.13 215.77,183.26 217.04,183.26 217.17,183.13 217.17,182.5 217.55,182.12 218.19,182.12 218.44,181.86 218.44,181.48 218.19,181.23
PWR_VDDNBA_PH on TOP: 210.82,175.64 206.38,180.09 206.38,185.8 207.65,187.07 207.65,190.88 206.38,192.15 206.38,195.58 206.63,195.83 207.49,195.83 207.67,195.66 207.67,194.82 207.85,194.64 209.73,194.64 210.01,194.92 210.01,195.61 210.3,195.9 211.39,195.9 211.46,195.83 211.46,192.79 211.33,192.66 209.17,192.66 208.66,192.15 208.66,191.64 209.93,190.37 211.33,190.37 212.09,189.61 212.09,188.21 212.72,187.58 215.14,187.58 215.26,187.45 215.26,181.23 215.65,180.85 217.42,180.85 218.31,179.96 218.31,177.42 216.53,175.64 215.65,175.64 215.14,176.15 215.14,177.29 214.88,177.55 212.6,177.55 212.09,177.04 212.09,176.53 211.2,175.64 ; 1 cut-out
PWR_VDDNBA_PH on BOTTOM: 210.95,175.64 206.5,180.09 206.5,186.06 207.65,187.2 207.65,190.5 206.25,191.9 206.25,194.06 207.01,194.82 211.07,194.82 211.33,194.56 211.33,189.87 213.61,187.58 214.88,187.58 215.26,187.2 215.26,181.23 215.65,180.85 217.3,180.85 218.31,179.83 218.31,177.42 216.53,175.64
PWR_VDDNBA_PH on L6: 207.26,194.56 210.85,194.56 211.3,194.11 211.3,189.76 213.49,187.58 214.86,187.58 215.26,187.17 215.26,181.23 215.65,180.85 217.42,180.85 218.31,179.96 218.31,177.42 216.53,175.64 210.82,175.64 206.38,180.09 206.38,185.8 207.52,186.94 207.52,190.88 206.38,192.02 206.38,193.68
PWR_VDDNBB_HG on BOTTOM: 223.39,188.34 223.14,188.59 223.14,190.25 223.77,190.88 225.43,190.88 225.55,190.75 225.55,190.25 225.17,189.87 225.17,188.47 225.04,188.34
PWR_VDDNBB_HG_A on BOTTOM: 225.93,188.34 225.81,188.47 225.81,189.74 226.69,190.63 228.47,190.63 228.6,190.75 228.6,192.28 228.73,192.41 230,192.41 230.12,192.28 230.12,191.01 228.98,189.87 228.98,188.59 228.73,188.34 ; 2 cut-outs
PWR_VDDNBB_PH on TOP: 227.71,175.51 227.46,175.77 227.46,177.29 227.2,177.55 225.43,177.55 224.92,177.04 224.92,176.53 224.66,176.28 223.27,176.28 222.88,176.66 222.88,179.96 225.02,182.09 225.02,187.45 225.2,187.63 227.81,187.63 228.6,188.42 228.6,189.87 228.85,190.12 229.87,190.12 230.12,190.37 230.12,191.26 230,191.39 228.63,191.39 228.63,194.64 228.73,194.74 230.89,194.74 231.27,194.36 231.27,176.91 229.87,175.51
PWR_VDDNBB_PH on BOTTOM: 224.16,175.39 222.88,176.66 222.88,179.96 225.04,182.12 225.04,187.48 225.2,187.63 227.79,187.63 227.8,187.64 228.87,187.64 229.29,188.06 229.29,189.31 229.46,189.48 229.87,189.48 230.38,189.99 230.38,192.53 230.25,192.66 228.75,192.66 228.63,192.79 228.63,195.96 228.7,196.04 230.15,196.04 232.16,194.03 232.16,177.8 229.74,175.39 ; 1 cut-out
PWR_VDDNBB_PH on L4: 226.95,194.82 230.76,194.82 231.27,194.31 231.27,176.91 230,175.64 223.9,175.64 223.14,176.4 223.14,180.34 225.04,182.25 225.04,189.36 226.19,190.5 226.19,194.06
PWR_VDDNBB_VCC on TOP: 220.9,202.64 220.73,202.82 220.73,204.14 220.75,204.17 221.01,204.17 221.03,204.14 221.03,203.43 221.11,203.35 221.18,203.35 221.26,203.43 221.26,204.17 221.46,204.17 221.54,204.09 221.54,202.69 221.59,202.64
PWR_VDDP on TOP: 146.69,199.14 146.18,199.64 146.18,204.98 144.53,204.98 144.02,205.49 144.02,206.12 143.13,207.01 141.86,207.01 141.6,207.26 141.6,208.79 141.73,208.91 150.5,208.91 151.51,207.9 151.51,204.72 153.42,202.82 153.42,199.52 153.03,199.14 ; 7 cut-outs
PWR_VDDP on BOTTOM: 146.75,199.1 146.23,199.62 146.23,202.64 146.69,203.1 152.58,203.1 153.34,202.34 153.34,199.85 152.59,199.1
PWR_VDDP_PH on TOP: 152.65,204.98 152.35,205.28 152.35,210.72 152.4,210.77 152.4,212.27 152.02,212.65 152.02,213.49 151.82,213.69 151.82,217.35 151.97,217.5 152.73,217.5 153.14,217.09 153.14,215.29 153.67,214.76 153.67,214.73 154.94,213.46 154.94,209.04 155.32,208.66 155.32,205.36 154.94,204.98 ; 2 cut-outs
PWR_VDDP_PH on BOTTOM: 152.15,208.53 151.76,208.91 151.76,210.57 152.48,211.28 152.48,213.33 152.22,213.59 151.82,213.59 151.73,213.67 151.73,217.33 151.85,217.45 152.6,217.45 152.68,217.37 152.68,216.59 152.63,216.59 152.55,216.51 152.55,214.17 152.6,214.12 153.95,214.12 154.56,213.51 154.56,211.2 154.43,211.07 154.43,208.79 154.18,208.53
PWR_VDDQ_LG on TOP: 221.21,137.92 220.98,138.15 220.98,138.53 221.21,138.76 221.92,138.76 222.15,138.99 223.19,138.99 223.24,138.94 223.24,138.84 222.33,137.92
PWR_VDDQ_PH on TOP: 223.7,113.49 217.04,120.14 217.04,125.22 217.3,125.48 222.5,125.48 222.63,125.35 222.63,122.02 222.94,121.72 229.31,121.72 229.36,121.67 229.36,119.25 230,118.62 230.89,118.62 231.27,118.24 231.27,114.6 231.24,114.58 231.24,114.07 230.66,113.49
PWR_VDDQ_PH on TOP: 221.03,135.86 220.93,135.97 220.93,137.03 221.46,137.57 222.5,137.57 223.49,138.56 223.65,138.56 223.7,138.51 223.7,137.59 221.97,135.86 ; 1 cut-out
PWR_VDDQ_PH on BOTTOM: 223.72,113.44 217.08,120.08 217.08,125.44 217.2,125.55 222.45,125.55 222.63,125.37 222.63,122.3 223.14,121.79 230.76,121.79 231.27,121.28 231.27,115.04 231.25,115.02 231.25,114.59 231.22,114.55 231.22,114.12 230.53,113.44
PWR_VDDQ_VLDOIN on TOP: 225.17,134.75 225.04,134.87 225.04,135.36 225.25,135.56 225.25,136.35 225.43,136.53 226.82,136.53 227.71,135.64 227.71,135.13 227.58,135 225.93,135 225.68,134.75 ; 1 cut-out
PWR_VDDQ_VTT on TOP: 226.09,136.8 225.3,137.59 225.3,137.67 225.17,137.79 225.17,138.43 225.3,138.56 226.06,138.56 226.57,138.05 227.08,138.05 227.33,138.3 227.33,139.7 227.71,140.08 229.62,140.08 229.87,139.83 229.87,137.13 229.54,136.8 ; 1 cut-out
RING2_CON on BOTTOM: 201.42,50.42 201.32,50.52 201.32,51.41 201.42,51.51 201.42,52.96 201.68,53.21 202.18,53.21 202.56,53.59 205.23,53.59 205.49,53.34 206.88,53.34 207.26,53.72 210.44,53.72 210.69,53.47 210.69,52.07 210.44,51.82 202.67,51.82 202.21,51.36 202.21,50.52 202.11,50.42 ; 2 cut-outs
RING2_CON on L6: 231.78,35.94 232.28,35.94 232.54,35.69 232.54,34.29 232.41,34.16 231.65,34.16 231.52,34.29 231.52,35.69
RING2_CON on L6: 209.8,53.47 209.8,51.31 210.06,51.05 211.46,51.05 211.84,51.44 211.84,53.34 211.46,53.72 210.06,53.72
SLEEVE_CON on TOP: 225.68,34.16 225.04,34.8 225.04,37.08 225.3,37.34 228.22,37.34 228.98,36.58 228.98,34.29 228.85,34.16
SLEEVE_CON on BOTTOM: 200.28,50.55 200.15,50.67 200.15,52.07 199.39,52.83 199.39,54.23 199.52,54.36 200.03,54.36 200.28,54.1 200.28,53.47 200.53,53.21 200.79,53.21 201.04,52.96 201.04,50.67 200.91,50.55 ; 1 cut-out
SLEEVE_CON on L6: 199.39,54.23 199.39,52.58 199.52,52.45 200.91,52.45 201.04,52.58 201.04,54.1 200.79,54.36 199.52,54.36
SLEEVE_CON on L6: 225.93,35.69 225.93,34.16 225.81,34.04 224.28,34.04 224.03,34.29 224.03,35.56 224.41,35.94 225.68,35.94
USBVCC31 on BOTTOM: 175.01,5.21 173.74,6.48 172.34,6.48 171.58,7.24 170.31,7.24 170.05,7.49 168.78,7.49 168.02,8.26 168.02,10.16 168.4,10.54 170.18,10.54 171.2,9.53 175.01,9.53 176.4,8.13 177.93,8.13 178.05,8 178.05,5.59 177.67,5.21 ; 2 cut-outs
USBVCC32 on TOP: 159,8.26 158.75,8.51 158.75,9.78 159,10.03 159.77,10.03 160.02,9.78 160.02,8.51 159.77,8.26
USBVCC32 on TOP: 173.99,3.05 173.53,3.5 173.53,4.75 173.86,5.08 173.86,7.37 173.61,7.62 173.61,8.38 173.86,8.64 174.24,8.64 176.15,6.73 176.53,6.73 176.66,6.6 176.66,5.33 175.9,4.57 175.9,3.3 175.64,3.05 ; 2 cut-outs
USBVCC32 on L6: 175.01,8.13 175.39,7.75 175.39,6.86 175.01,6.48 159.89,6.48 158.88,7.49 158.88,10.03 159,10.16 160.02,10.16 160.4,9.78 160.4,8.51 160.78,8.13
USBVCCTP on TOP: 186.44,12.32 186.06,12.7 186.06,14.22 185.7,14.58 185.7,14.86 185.83,14.99 187.71,14.99 188.34,14.35 188.34,12.57 188.09,12.32
USBVCCTP on BOTTOM: 183.81,6.81 183.65,6.96 183.65,7.49 184.15,7.99 184.15,9.78 186.06,11.68 186.06,13.59 186.31,13.84 187.83,13.84 188.34,13.34 188.34,8.13 188.21,8 186.08,8 185.83,7.75 185.83,7.04 185.6,6.81 ; 1 cut-out
V_3P3_PCIVAUX on TOP: 189.28,35.81 189.18,35.92 189.18,37.47 189.31,37.59 189.31,39.32 189.53,39.55 189.53,42.06 189.59,42.11 191.01,42.11 191.08,42.19 191.08,42.32 191.06,42.34 189.56,42.34 189.53,42.37 189.53,42.44 189.61,42.52 191.06,42.52 191.08,42.49 191.44,42.49 191.74,42.19 191.74,41.22 191.22,40.7 191.22,39.65 191.08,39.51 191.08,39.5 190.96,39.37 190.96,37.92 190.63,37.59 190.63,35.94 190.5,35.81 ; 3 cut-outs
V_3P3_PCIVAUX on TOP: 189.53,59.36 189.51,59.39 189.51,59.61 189.53,59.64 191.06,59.64 191.11,59.69 191.11,59.77 191.03,59.84 189.51,59.84 189.48,59.87 189.48,60.3 190.22,61.04 190.22,64.95 190.68,65.41 192.41,65.41 193.68,64.14 193.68,60.83 193.29,60.45 192.91,60.45 191.91,59.45 191.22,59.45 191.13,59.36 ; 3 cut-outs
V_3P3_PCIVAUX on BOTTOM: 189.74,39.12 189.48,39.37 189.48,41.78 188.59,42.67 188.59,58.04 192.02,61.47 193.29,61.47 193.68,61.09 193.68,60.58 190.12,57.02 190.12,42.93 190.63,42.42 190.63,41.27 190.92,40.98 190.92,39.41 190.63,39.12
V_5HDD on TOP: 82.68,17.65 80.26,20.07 80.26,26.92 81.15,27.81 87.25,27.81 87.38,27.69 87.38,25.4 87.63,25.15 87.63,23.11 88.14,22.61 88.14,20.24 89.32,19.06 89.32,17.89 89.08,17.65 ; 3 cut-outs
WOOF_AVDD2_1 on BOTTOM: 196.32,28.42 196.29,28.45 195.07,28.45 194.94,28.57 194.94,30.1 195.2,30.35 195.2,31.24 195.45,31.5 196.22,31.5 196.44,31.27 196.44,29.84 196.62,29.67 196.98,29.67 197.28,29.36 197.28,28.52 197.18,28.42 ; 4 cut-outs
WOOF_L+_C on TOP: 201.32,5.74 201.19,5.87 201.19,8.86 202.67,10.34 204.11,10.34 204.24,10.21 204.24,9.5 203.76,9.02 203.73,9.02 202.46,7.75 202.01,7.75 201.8,7.54 201.8,5.82 201.73,5.74
WOOF_L+_C on BOTTOM: 202.31,8.76 200.15,10.92 197.87,10.92 196.34,12.45 194.82,12.45 194.44,12.83 194.44,13.59 194.82,13.97 197.49,13.97 197.87,13.59 197.87,12.83 198.25,12.45 200.91,12.45 202.95,10.41 204.09,10.41 204.34,10.16 204.34,8.89 204.22,8.76 ; 2 cut-outs
WOOF_L-_C on TOP: 200.25,5.77 200.2,5.82 200.2,11.53 200.66,11.99 203.43,11.99 203.73,11.68 203.73,10.95 203.53,10.74 202.64,10.74 200.81,8.92 200.81,5.82 200.76,5.77
WOOF_OUT_A1 on TOP: 198.27,19.3 198.09,19.48 198.09,20.93 198.22,21.06 198.93,21.06 199.19,20.8 199.19,19.43 199.06,19.3
WOOF_OUT_A1 on BOTTOM: 198.42,15.95 198.22,16.15 198.22,20.95 198.42,21.16 199.06,21.16 200.53,19.68 200.53,16.18 200.3,15.95 ; 3 cut-outs
WOOF_OUT_A1_L on TOP: 200.53,12.57 200.41,12.7 200.41,13.72 200.53,13.84 203.71,13.84 203.96,13.59 203.96,12.83 203.71,12.57
WOOF_OUT_A1_L on BOTTOM: 202.18,12.7 201.93,12.95 198.63,12.95 198.37,13.21 198.37,14.48 198.75,14.86 200.15,14.86 201.04,15.75 201.8,15.75 201.93,15.62 201.93,14.73 202.56,14.1 203.71,14.1 203.96,13.84 203.96,12.83 203.84,12.7 ; 1 cut-out
WOOF_OUT_B1 on TOP: 197.21,19.56 196.82,19.94 196.82,21.01 196.98,21.16 197.46,21.16 197.71,20.9 197.71,19.68 197.59,19.56
WOOF_OUT_B1 on BOTTOM: 195.91,15.37 195.63,15.65 195.63,18.95 196.34,19.66 196.34,20.7 196.72,21.08 197.66,21.08 197.79,20.95 197.79,18.92 197.76,18.9 197.76,15.6 197.54,15.37 ; 3 cut-outs
WOOF_OUT_C1 on TOP: 193.17,15.49 192.46,16.21 192.46,19.25 193.41,20.21 193.42,20.21 193.66,20.45 193.68,20.45 193.68,20.95 193.8,21.08 194.18,21.08 194.31,20.95 194.31,20.32 194.42,20.21 194.42,19.19 194.44,19.18 194.44,17.27 194.82,16.89 195.2,16.89 195.33,16.76 195.33,15.62 195.2,15.49 ; 3 cut-outs
WOOF_OUT_C1_L on TOP: 193.8,9.65 193.42,10.03 193.42,13.97 193.55,14.1 196.37,14.1 196.72,13.74 196.72,12.83 196.52,12.62 195.53,12.62 195.25,12.34 195.25,9.8 195.1,9.65 ; 1 cut-out
WOOF_OUT_D1 on TOP: 190.25,16.36 190.12,16.48 190.12,20.17 190.73,20.78 191.95,20.78 192.33,21.16 193.24,21.16 193.32,21.08 193.32,20.75 192.15,19.58 192.15,16.43 192.07,16.36 ; 3 cut-outs
WOOF_R+_C on TOP: 191.52,10.29 190.63,11.18 190.63,13.34 190.37,13.59 190.37,14.86 190.42,14.91 191.97,14.91 192.15,14.73 192.15,13.08 192.91,12.32 192.91,10.41 192.79,10.29 ; 2 cut-outs
WOOF_R+_C on TOP: 199.29,5.71 199.15,5.86 199.15,8.4 199.14,8.41 199.14,8.76 198.08,9.82 198.08,10.25 198.37,10.54 199.27,10.54 199.77,10.03 199.77,5.84 199.64,5.71
WOOF_R+_C on BOTTOM: 192.02,8.89 191.64,9.27 191.64,12.06 191.77,12.19 193.17,12.19 193.42,11.94 193.42,10.92 193.93,10.41 198.37,10.41 198.5,10.54 199.77,10.54 200.15,10.16 200.15,9.14 199.9,8.89
WOOF_R-_C on TOP: 198.35,5.59 198.2,5.74 198.2,7.54 198.09,7.65 197.84,7.65 195.91,9.58 195.91,11.15 195.68,11.38 195.68,12.01 195.76,12.09 196.44,12.09 196.47,12.06 198.12,12.06 198.25,11.94 198.25,11.18 197.74,10.67 197.74,9.65 198.75,8.64 198.75,5.71 198.63,5.59

Small or netless copper shapes (teardrops, artwork), in the pictures only: 5 on TOP, 5 on BOTTOM

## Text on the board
Ref Des/Silkscreen Bottom: F22:1.5A/6V
Ref Des/Silkscreen Top: Dell PN:4KVVM | Rev:A00 | UT1202 | 3 | 5 | 1 | 2 | 6 | 4 | JUMPER | JMP1 | PASSWORD_CLR | SERVICE_MODE | CMOS_CLR | FUNCTION | 1-2 OPEN:DEFAULT | 3-4 OPEN:PASSWORD RESET | 5-6 OPEN:DEFAULT | 1-2 SHORT:ME DISABLE | 3-4 SHORT:DEFAULT | 5-6 SHORT:RTC_CMOS RESET | OPERATION | X2:48MHZ | X1:32.768KHZ | X99:27MHZ | X3:25MHZ | F3:1.1A/24V | F2:1.5A/6V | F23:1.5A/6V | F21:1.1A/24V | X100:32.768KHZ | PASR/CY17 Thanos | MADE IN TAIWAN | 16544-1 | 4KVVM
User.29: GND | AGND | 1D2V_MEM_S3
User.30: GND | AGND | 1D2V_MEM_S3
User.31: 1D35V_MEM_VGA | 1V_VDDCI_VGA | GND | 1V_VDDC_VGA | 1D05V_S0 | 1D05V_S5 | 1V_VDDCR_CPU | 1D2V_MEM_S3 | 1V_VDDCR_SOC | AGND
User.32: Board Accuracy Check,Mar 22 13:26:07 2017,Passed | Dummy-Static-No Shape On Layer Check,Mar 22 13:26:07 2017,2 errors | Solder Bump Check,Sep 30 14:54:17 2016,125 errors | Split Plane Check,Mar 22 13:26:07 2017,2 errors
